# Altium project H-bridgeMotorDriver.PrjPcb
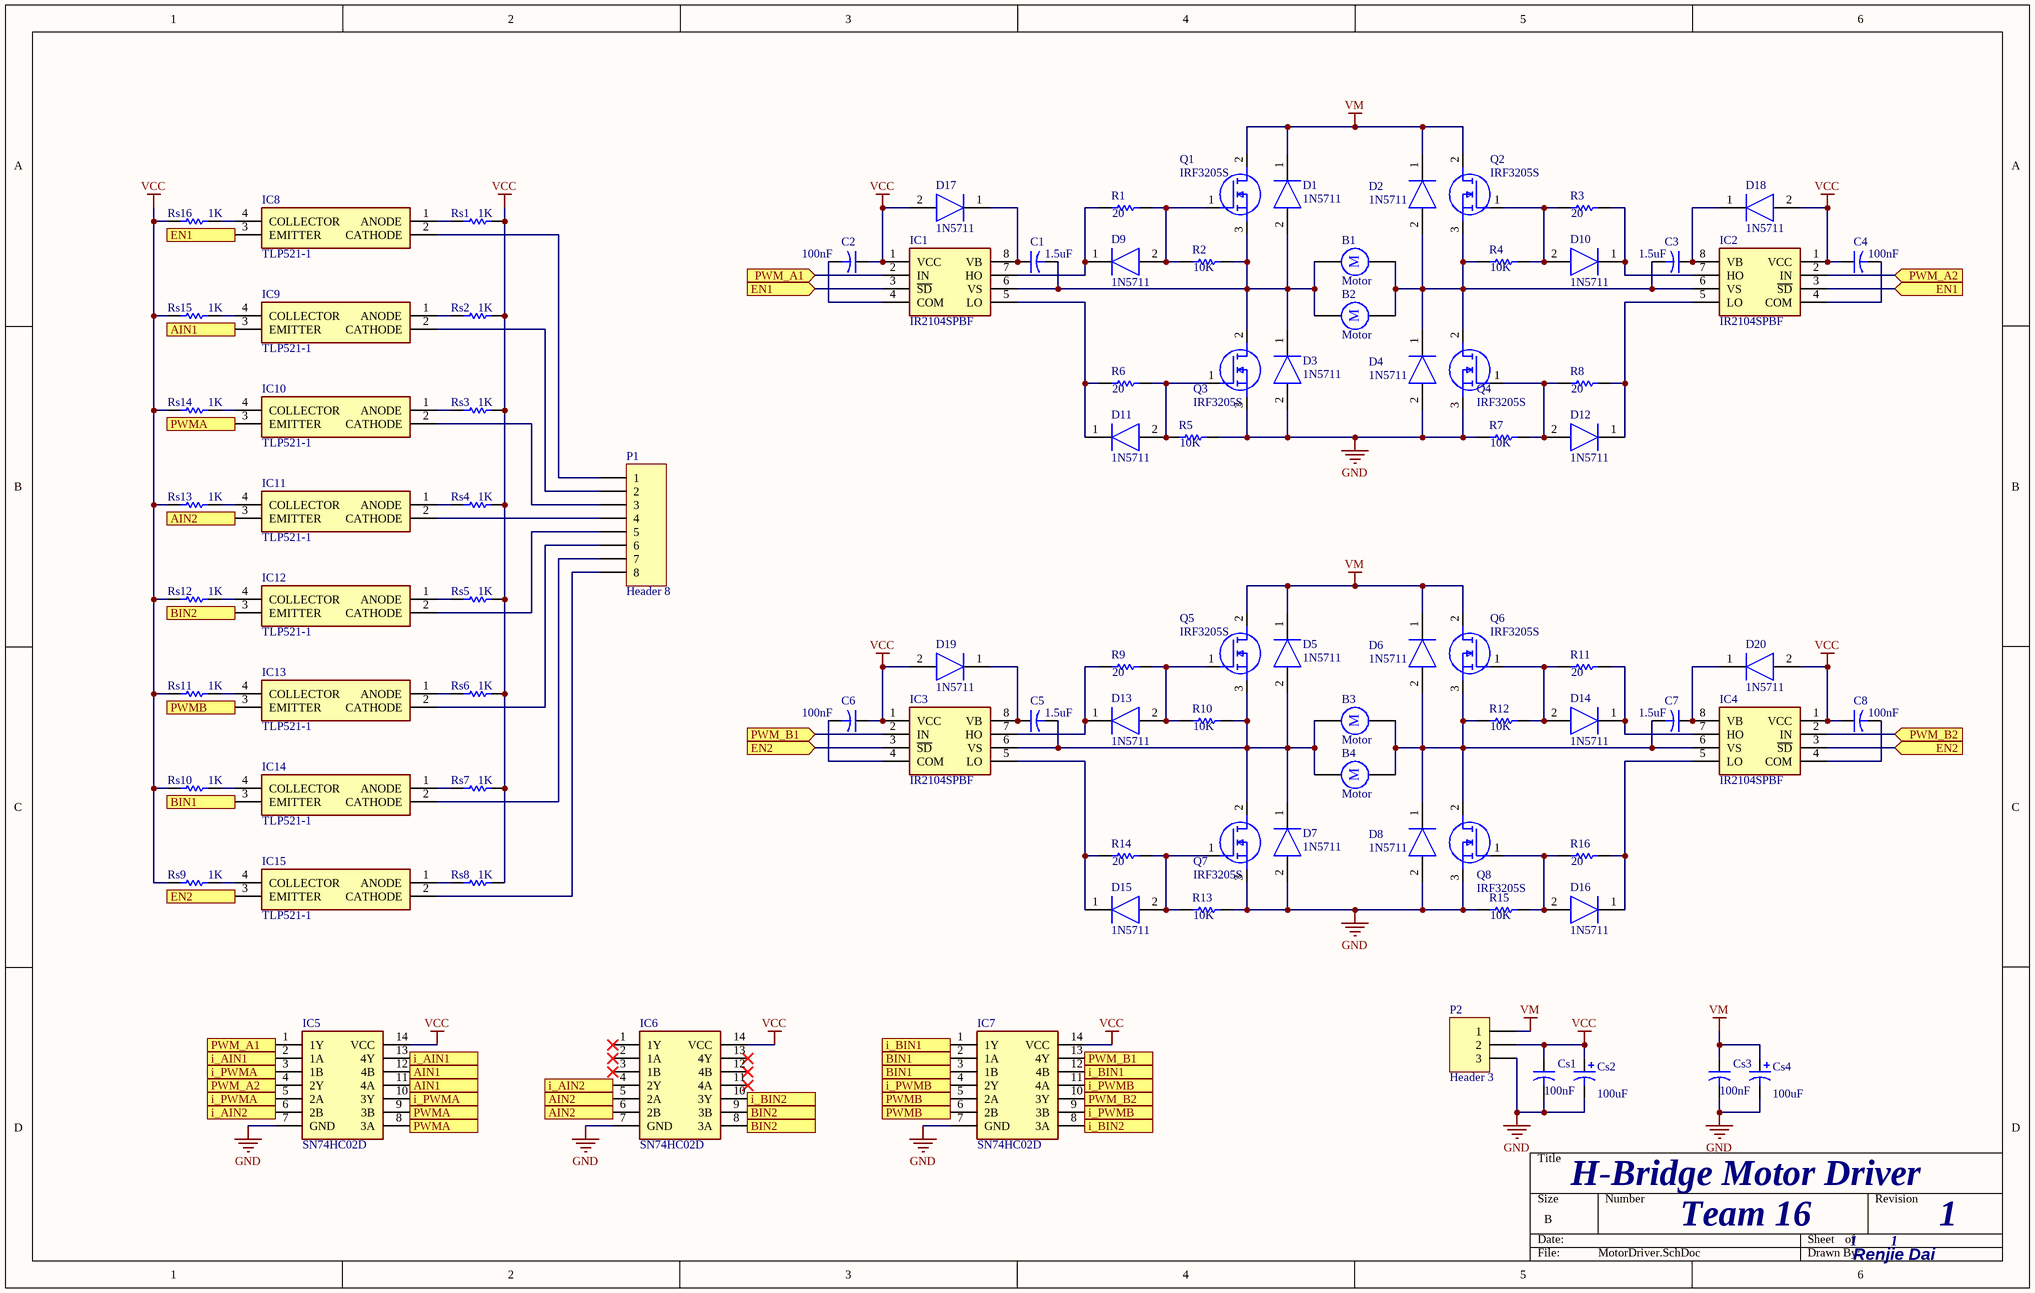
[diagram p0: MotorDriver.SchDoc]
1 sheet, 93 parts. Net scope: flat (ports and power ports of the same name join across sheets).
Board file: MotorDriver.PcbDoc

## Sheet MotorDriver.SchDoc
size B

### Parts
B1  Motor  [RB5-10.5]
B2  Motor  [RB5-10.5]
B3  Motor  [RB5-10.5]
B4  Motor  [RB5-10.5]
C1  value 1.5uF  [CAPR5-4X5]
C2  value 100nF  [CAPR5-4X5]
C3  value 1.5uF  [CAPR5-4X5]
C4  value 100nF  [CAPR5-4X5]
C5  value 1.5uF  [CAPR5-4X5]
C6  value 100nF  [CAPR5-4X5]
C7  value 1.5uF  [CAPR5-4X5]
C8  value 100nF  [CAPR5-4X5]
Cs1  value 100nF  [CAPR5-4X5]
Cs2  value 100uF  [RB7.6-15]
Cs3  value 100nF  [CAPR5-4X5]
Cs4  value 100uF  [RB7.6-15]
D1  1N5711  [DIOAD810W51L378D176P]
D2  1N5711  [DIOAD810W51L378D176P]
D3  1N5711  [DIOAD810W51L378D176P]
D4  1N5711  [DIOAD810W51L378D176P]
D5  1N5711  [DIOAD810W51L378D176P]
D6  1N5711  [DIOAD810W51L378D176P]
D7  1N5711  [DIOAD810W51L378D176P]
D8  1N5711  [DIOAD810W51L378D176P]
D9  1N5711  [DIOAD810W51L378D176P]
D10  1N5711  [DIOAD810W51L378D176P]
D11  1N5711  [DIOAD810W51L378D176P]
D12  1N5711  [DIOAD810W51L378D176P]
D13  1N5711  [DIOAD810W51L378D176P]
D14  1N5711  [DIOAD810W51L378D176P]
D15  1N5711  [DIOAD810W51L378D176P]
D16  1N5711  [DIOAD810W51L378D176P]
D17  1N5711  [DIOAD810W51L378D176P]
D18  1N5711  [DIOAD810W51L378D176P]
D19  1N5711  [DIOAD810W51L378D176P]
D20  1N5711  [DIOAD810W51L378D176P]
IC1  IR2104SPBF  [SOIC127P600X175-8N]
IC2  IR2104SPBF  [SOIC127P600X175-8N]
IC3  IR2104SPBF  [SOIC127P600X175-8N]
IC4  IR2104SPBF  [SOIC127P600X175-8N]
IC5  SN74HC02D  [SOIC127P600X175-14N]
IC6  SN74HC02D  [SOIC127P600X175-14N]
IC7  SN74HC02D  [SOIC127P600X175-14N]
IC8  TLP521-1  [DIP762W60P254L448H380Q4N]
IC9  TLP521-1  [DIP762W60P254L448H380Q4N]
IC10  TLP521-1  [DIP762W60P254L448H380Q4N]
IC11  TLP521-1  [DIP762W60P254L448H380Q4N]
IC12  TLP521-1  [DIP762W60P254L448H380Q4N]
IC13  TLP521-1  [DIP762W60P254L448H380Q4N]
IC14  TLP521-1  [DIP762W60P254L448H380Q4N]
IC15  TLP521-1  [DIP762W60P254L448H380Q4N]
P1  Header 8  [HDR1X8]
P2  Header 3  [HDR1X3]
Q1  IRF3205S  [TO254P469X1042X1930-3P]
Q2  IRF3205S  [TO254P469X1042X1930-3P]
Q3  IRF3205S  [TO254P469X1042X1930-3P]
Q4  IRF3205S  [TO254P469X1042X1930-3P]
Q5  IRF3205S  [TO254P469X1042X1930-3P]
Q6  IRF3205S  [TO254P469X1042X1930-3P]
Q7  IRF3205S  [TO254P469X1042X1930-3P]
Q8  IRF3205S  [TO254P469X1042X1930-3P]
R1  value 20  [AXIAL-0.3]
R2  value 10K  [AXIAL-0.3]
R3  value 20  [AXIAL-0.3]
R4  value 10K  [AXIAL-0.3]
R5  value 10K  [AXIAL-0.3]
R6  value 20  [AXIAL-0.3]
R7  value 10K  [AXIAL-0.3]
R8  value 20  [AXIAL-0.3]
R9  value 20  [AXIAL-0.3]
R10  value 10K  [AXIAL-0.3]
R11  value 20  [AXIAL-0.3]
R12  value 10K  [AXIAL-0.3]
R13  value 10K  [AXIAL-0.3]
R14  value 20  [AXIAL-0.3]
R15  value 10K  [AXIAL-0.3]
R16  value 20  [AXIAL-0.3]
Rs1  value 1K  [AXIAL-0.3]
Rs2  value 1K  [AXIAL-0.3]
Rs3  value 1K  [AXIAL-0.3]
Rs4  value 1K  [AXIAL-0.3]
Rs5  value 1K  [AXIAL-0.3]
Rs6  value 1K  [AXIAL-0.3]
Rs7  value 1K  [AXIAL-0.3]
Rs8  value 1K  [AXIAL-0.3]
Rs9  value 1K  [AXIAL-0.3]
Rs10  value 1K  [AXIAL-0.3]
Rs11  value 1K  [AXIAL-0.3]
Rs12  value 1K  [AXIAL-0.3]
Rs13  value 1K  [AXIAL-0.3]
Rs14  value 1K  [AXIAL-0.3]
Rs15  value 1K  [AXIAL-0.3]
Rs16  value 1K  [AXIAL-0.3]

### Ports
AIN1 (in), AIN1 (out), AIN2 (in), AIN2 (out), BIN1 (in), BIN1 (out), BIN2 (in), BIN2 (out), EN1 (in), EN1 (out), EN2 (in), EN2 (out), i_AIN1 (in), i_AIN1 (out), i_AIN2 (in), i_AIN2 (out), i_BIN1 (in), i_BIN1 (out), i_BIN2 (in), i_BIN2 (out), i_PWMA (in), i_PWMA (out), i_PWMB (in), i_PWMB (out), PWM_A1 (in), PWM_A1 (out), PWM_A2 (in), PWM_A2 (out), PWM_B1 (in), PWM_B1 (out), PWM_B2 (in), PWM_B2 (out), PWMA (in), PWMA (out), PWMB (in), PWMB (out)

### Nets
GND: Cs1.2 Cs2.2 Cs3.2 Cs4.2 D3.2(A) D4.2(A) D7.2(A) D8.2(A) IC5.7(GND) IC6.7(GND) IC7.7(GND) P2.3 Q3.3(S) Q4.3(S) Q7.3(S) Q8.3(S) R5.2 R7.1 R13.2 R15.1
VCC: C2.1 C4.1 C6.1 C8.1 Cs1.1 Cs2.1 D17.2(A) D18.2(A) D19.2(A) D20.2(A) IC1.1(VCC) IC2.1(VCC) IC3.1(VCC) IC4.1(VCC) IC5.14(VCC) IC6.14(VCC) IC7.14(VCC) P2.2 Rs1.2 Rs2.2 Rs3.2 Rs4.2 Rs5.2 Rs6.2 Rs7.2 Rs8.2 Rs9.1 Rs10.1 Rs11.1 Rs12.1 Rs13.1 Rs14.1 Rs15.1 Rs16.1
VM: Cs3.1 Cs4.1 D1.1(K) D2.1(K) D5.1(K) D6.1(K) P2.1 Q1.2(D) Q2.2(D) Q5.2(D) Q6.2(D)
NetB1_1: B1.1 B2.1 C1.2 D1.2(A) D3.1(K) IC1.6(VS) Q1.3(S) Q3.2(D) R2.2
NetB1_2: B1.2 B2.2 C3.2 D2.2(A) D4.1(K) IC2.6(VS) Q2.3(S) Q4.2(D) R4.1
NetB3_1: B3.1 B4.1 C5.2 D5.2(A) D7.1(K) IC3.6(VS) Q5.3(S) Q7.2(D) R10.2
NetB3_2: B3.2 B4.2 C7.2 D6.2(A) D8.1(K) IC4.6(VS) Q6.3(S) Q8.2(D) R12.1
NetC1_1: C1.1 D17.1(K) IC1.8(VB)
NetC2_2: C2.2 IC1.4(COM)
NetC3_1: C3.1 D18.1(K) IC2.8(VB)
NetC4_2: C4.2 IC2.4(COM)
NetC5_1: C5.1 D19.1(K) IC3.8(VB)
NetC6_2: C6.2 IC3.4(COM)
NetC7_1: C7.1 D20.1(K) IC4.8(VB)
NetC8_2: C8.2 IC4.4(COM)
NetD9_1: D9.1(K) IC1.7(HO) R1.1
NetD9_2: D9.2(A) Q1.1(G) R1.2 R2.1
NetD10_1: D10.1(K) IC2.7(HO) R3.2
NetD10_2: D10.2(A) Q2.1(G) R3.1 R4.2
NetD11_1: D11.1(K) IC1.5(LO) R6.1
NetD11_2: D11.2(A) Q3.1(G) R5.1 R6.2
NetD12_1: D12.1(K) IC2.5(LO) R8.2
NetD12_2: D12.2(A) Q4.1(G) R7.2 R8.1
NetD13_1: D13.1(K) IC3.7(HO) R9.1
NetD13_2: D13.2(A) Q5.1(G) R9.2 R10.1
NetD14_1: D14.1(K) IC4.7(HO) R11.2
NetD14_2: D14.2(A) Q6.1(G) R11.1 R12.2
NetD15_1: D15.1(K) IC3.5(LO) R14.1
NetD15_2: D15.2(A) Q7.1(G) R13.1 R14.2
NetD16_1: D16.1(K) IC4.5(LO) R16.2
NetD16_2: D16.2(A) Q8.1(G) R15.2 R16.1
NetIC1_2: IC1.2(IN) IC5.1(1Y) ; port PWM_A1
NetIC1_3: IC1.3(~{SD}) IC2.3(~{SD}) IC8.3(EMITTER) ; port EN1
NetIC2_2: IC2.2(IN) IC5.4(2Y) ; port PWM_A2
NetIC3_2: IC3.2(IN) IC7.13(4Y) ; port PWM_B1
NetIC3_3: IC3.3(~{SD}) IC4.3(~{SD}) IC15.3(EMITTER) ; port EN2
NetIC4_2: IC4.2(IN) IC7.10(3Y) ; port PWM_B2
NetIC5_2: IC5.2(1A) IC5.13(4Y) ; port i_AIN1
NetIC5_3: IC5.3(1B) IC5.5(2A) IC5.10(3Y) ; port i_PWMA
NetIC5_6: IC5.6(2B) IC6.4(2Y) ; port i_AIN2
NetIC5_8: IC5.8(3A) IC5.9(3B) IC10.3(EMITTER) ; port PWMA
NetIC5_11: IC5.11(4A) IC5.12(4B) IC9.3(EMITTER) ; port AIN1
NetIC6_5: IC6.5(2A) IC6.6(2B) IC11.3(EMITTER) ; port AIN2
NetIC6_8: IC6.8(3A) IC6.9(3B) IC12.3(EMITTER) ; port BIN2
NetIC6_10: IC6.10(3Y) IC7.8(3A) ; port i_BIN2
NetIC7_1: IC7.1(1Y) IC7.12(4B) ; port i_BIN1
NetIC7_2: IC7.2(1A) IC7.3(1B) IC14.3(EMITTER) ; port BIN1
NetIC7_4: IC7.4(2Y) IC7.9(3B) IC7.11(4A) ; port i_PWMB
NetIC7_5: IC7.5(2A) IC7.6(2B) IC13.3(EMITTER) ; port PWMB
NetIC8_1: IC8.1(ANODE) Rs1.1
NetIC8_2: IC8.2(CATHODE) P1.1
NetIC8_4: IC8.4(COLLECTOR) Rs16.2
NetIC9_1: IC9.1(ANODE) Rs2.1
NetIC9_2: IC9.2(CATHODE) P1.2
NetIC9_4: IC9.4(COLLECTOR) Rs15.2
NetIC10_1: IC10.1(ANODE) Rs3.1
NetIC10_2: IC10.2(CATHODE) P1.3
NetIC10_4: IC10.4(COLLECTOR) Rs14.2
NetIC11_1: IC11.1(ANODE) Rs4.1
NetIC11_2: IC11.2(CATHODE) P1.4
NetIC11_4: IC11.4(COLLECTOR) Rs13.2
NetIC12_1: IC12.1(ANODE) Rs5.1
NetIC12_2: IC12.2(CATHODE) P1.5
NetIC12_4: IC12.4(COLLECTOR) Rs12.2
NetIC13_1: IC13.1(ANODE) Rs6.1
NetIC13_2: IC13.2(CATHODE) P1.6
NetIC13_4: IC13.4(COLLECTOR) Rs11.2
NetIC14_1: IC14.1(ANODE) Rs7.1
NetIC14_2: IC14.2(CATHODE) P1.7
NetIC14_4: IC14.4(COLLECTOR) Rs10.2
NetIC15_1: IC15.1(ANODE) Rs8.1
NetIC15_2: IC15.2(CATHODE) P1.8
NetIC15_4: IC15.4(COLLECTOR) Rs9.2

Not connected (* = marked no-connect by the designer): IC6 1(1Y)* 2(1A)* 3(1B)* 11(4A)* 12(4B)* 13(4Y)*

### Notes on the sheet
- H-Bridge Motor Driver
- Team 16
- 1
- Renjie Dai

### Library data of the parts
B1-B4 = Motor: Motor, General Kind
C1-C8 Cs1 Cs3 = Cap2: Capacitor
Cs2 Cs4 = Cap Pol1: Polarized Capacitor (Radial)
D1-D20 = 1N5711: Diode; Manufacturer_Name: STMicroelectronics; Allied_Number: 70013815
IC1-IC4 = IR2104SPBF: Integrated Circuit; Manufacturer_Name: Infineon; Allied_Number: 70017129
IC5-IC7 = SN74HC02D: Integrated Circuit; Manufacturer_Name: Texas Instruments
IC8-IC15 = TLP521-1: Integrated Circuit; Manufacturer_Name: Toshiba
P1 = Header 8: Header, 8-Pin
P2 = Header 3: Header, 3-Pin
Q1-Q8 = IRF3205S: MOSFET (N-Channel); Manufacturer_Name: International Rectifier
R1-R16 Rs1-Rs16 = Res1: Resistor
